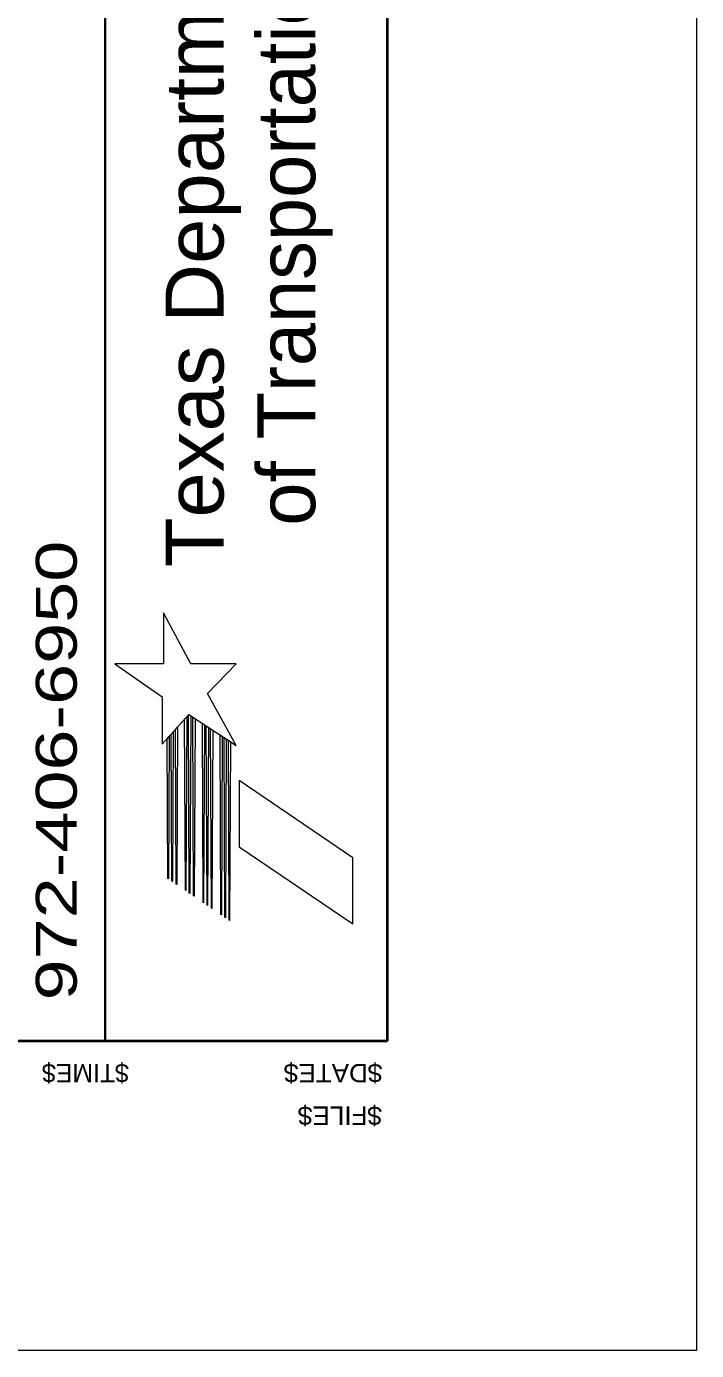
# Model space of a CAD drawing. Extents: x 2363323 to 2367082, y 6956018 to 6980837.
# Drawn here: x 2366706.6 to 2366923.3, y 6957200.9 to 6957628.9 of the extents above; entities that cross this region are included whole.
import ezdxf
from ezdxf.enums import TextEntityAlignment as Align

# ---------------------------------------------------------------- set-up
doc = ezdxf.new("R2010")
doc.units = 0
doc.header["$LTSCALE"] = 4.1
doc.layers.add('60', color=7, linetype='Continuous')
for name, color, linetype, lineweight in [('61', 7, 'Continuous', 40), ('62', 7, 'Continuous', 13), ('63', 7, 'Continuous', 13)]:
    doc.layers.add(name, color=color, linetype=linetype, lineweight=lineweight)

msp = doc.modelspace()

# ---------------------------------------------------------------- linework, layer by layer
at = {"layer": '61'}
msp.add_line((2366823.34, 6957300.912), (2363423.186, 6957300.912), dxfattribs=at)
msp.add_line((2366823.34, 6957300.912), (2363423.186, 6957300.912), dxfattribs=at)
at = {"layer": '61', "lineweight": 13}
msp.add_lwpolyline([(2366923.344, 6957200.912), (2363323.182, 6957200.912), (2363323.182, 6980256.082)], dxfattribs=at)
at = {"layer": '62'}
msp.add_line((2366923.344, 6980256.082), (2366923.344, 6957200.912), dxfattribs=at)
at = {"layer": '62', "lineweight": 40}
msp.add_line((2366823.34, 6980156.078), (2366823.34, 6957300.912), dxfattribs=at)
at = {"layer": '62', "lineweight": 35}
msp.add_line((2366732.124, 6957696.747), (2366732.124, 6957300.911), dxfattribs=at)
at = {"layer": '62'}
for points in [[(2366735.232, 6957422.933), (2366750.561, 6957412.228), (2366750.563, 6957396.883), (2366759.12, 6957406.529), (2366774.469, 6957396.543), (2366765.182, 6957413.29), (2366774.47, 6957422.933), (2366759.834, 6957422.932), (2366750.93, 6957439.342), (2366750.938, 6957422.933)], [(2366755.073, 6957351.668), (2366754.856, 6957401.714), (2366755.491, 6957402.424), (2366755.251, 6957351.586)], [(2366758.012, 6957349.677), (2366757.728, 6957404.953), (2366758.46, 6957405.755), (2366758.199, 6957349.572)], [(2366759.296, 6957348.786), (2366758.999, 6957406.355), (2366759.122, 6957406.516), (2366759.767, 6957406.093), (2366759.494, 6957348.688)], [(2366760.697, 6957347.858), (2366760.422, 6957405.687), (2366761.172, 6957405.193), (2366760.879, 6957347.778)], [(2366763.766, 6957345.756), (2366763.512, 6957403.678), (2366764.233, 6957403.207), (2366763.937, 6957345.65)], [(2366765.049, 6957344.858), (2366764.799, 6957402.827), (2366765.504, 6957402.372), (2366765.228, 6957344.777)], [(2366752.378, 6957353.503), (2366752.18, 6957398.688), (2366752.795, 6957399.414), (2366752.568, 6957353.404)], [(2366753.677, 6957352.622), (2366753.45, 6957400.133), (2366754.102, 6957400.854), (2366753.842, 6957352.499)], [(2366766.434, 6957343.936), (2366766.186, 6957401.922), (2366766.9, 6957401.454), (2366766.628, 6957343.832)], [(2366769.515, 6957341.836), (2366769.252, 6957399.932), (2366769.932, 6957399.482), (2366769.693, 6957341.73)], [(2366770.776, 6957340.943), (2366770.541, 6957399.099), (2366771.212, 6957398.653), (2366770.971, 6957340.845)], [(2366772.186, 6957340.023), (2366771.923, 6957398.187), (2366772.607, 6957397.729), (2366772.346, 6957339.906)], [(2366775.42, 6957363.783), (2366812.142, 6957338.802), (2366812.142, 6957360.205), (2366775.414, 6957385.173)]]:
    msp.add_lwpolyline(points, close=True, dxfattribs=at)
at = {"layer": '63'}
msp.add_line((2366923.344, 6980256.082), (2366923.344, 6957200.912), dxfattribs=at)
at = {"layer": '63', "lineweight": 40}
msp.add_line((2366823.34, 6980156.078), (2366823.34, 6957300.912), dxfattribs=at)
at = {"layer": '63'}
for points in [[(2366735.232, 6957422.933), (2366750.561, 6957412.228), (2366750.563, 6957396.883), (2366759.12, 6957406.529), (2366774.469, 6957396.543), (2366765.182, 6957413.29), (2366774.47, 6957422.933), (2366759.834, 6957422.932), (2366750.93, 6957439.342), (2366750.938, 6957422.933)], [(2366755.073, 6957351.668), (2366754.856, 6957401.714), (2366755.491, 6957402.424), (2366755.251, 6957351.586)], [(2366758.012, 6957349.677), (2366757.728, 6957404.953), (2366758.46, 6957405.755), (2366758.199, 6957349.572)], [(2366759.296, 6957348.786), (2366758.999, 6957406.355), (2366759.122, 6957406.516), (2366759.767, 6957406.093), (2366759.494, 6957348.688)], [(2366760.697, 6957347.858), (2366760.422, 6957405.687), (2366761.172, 6957405.193), (2366760.879, 6957347.778)], [(2366763.766, 6957345.756), (2366763.512, 6957403.678), (2366764.233, 6957403.207), (2366763.937, 6957345.65)], [(2366765.049, 6957344.858), (2366764.799, 6957402.827), (2366765.504, 6957402.372), (2366765.228, 6957344.777)], [(2366752.378, 6957353.503), (2366752.18, 6957398.688), (2366752.795, 6957399.414), (2366752.568, 6957353.404)], [(2366753.677, 6957352.622), (2366753.45, 6957400.133), (2366754.102, 6957400.854), (2366753.842, 6957352.499)], [(2366766.434, 6957343.936), (2366766.186, 6957401.922), (2366766.9, 6957401.454), (2366766.628, 6957343.832)], [(2366769.515, 6957341.836), (2366769.252, 6957399.932), (2366769.932, 6957399.482), (2366769.693, 6957341.73)], [(2366770.776, 6957340.943), (2366770.541, 6957399.099), (2366771.212, 6957398.653), (2366770.971, 6957340.845)], [(2366772.186, 6957340.023), (2366771.923, 6957398.187), (2366772.607, 6957397.729), (2366772.346, 6957339.906)], [(2366775.42, 6957363.783), (2366812.142, 6957338.802), (2366812.142, 6957360.205), (2366775.414, 6957385.173)]]:
    msp.add_lwpolyline(points, close=True, dxfattribs=at)

# ---------------------------------------------------------------- texts
at = {"layer": '60'}
msp.add_text('$TIME$', height=6, rotation=180, dxfattribs=at).set_placement((2366739.775, 6957293.585))
at = {"layer": '60', "width": 1.05}
for s, p in [('$DATE$', (2366821.741, 6957293.585)), ('$FILE$', (2366821.606, 6957279.794))]:
    msp.add_text(s, height=6, rotation=180, dxfattribs=at).set_placement(p)
at = {"layer": '62', "width": 1.05}
msp.add_text('Texas Department', height=18.76, rotation=90, dxfattribs=at).set_placement((2366770.36, 6957562.432), align=Align.CENTER)
at = {"layer": '62'}
msp.add_text('of Transportation', height=18.76, rotation=90, dxfattribs=at).set_placement((2366800.012, 6957562.362), align=Align.CENTER)
at = {"layer": '62', "width": 1.35}
msp.add_text('972-406-6950', height=13.22, rotation=90, dxfattribs=at).set_placement((2366722.881, 6957314.081))
at = {"layer": '63', "width": 1.05}
msp.add_text('Texas Department', height=18.76, rotation=90, dxfattribs=at).set_placement((2366770.36, 6957562.432), align=Align.CENTER)
at = {"layer": '63'}
msp.add_text('of Transportation', height=18.76, rotation=90, dxfattribs=at).set_placement((2366800.012, 6957562.362), align=Align.CENTER)

doc.saveas('drawing.dxf')
